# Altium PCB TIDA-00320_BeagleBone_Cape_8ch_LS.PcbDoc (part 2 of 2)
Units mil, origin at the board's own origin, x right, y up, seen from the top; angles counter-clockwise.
Board outline 6250 x 2150 mil, 2 copper layers (Top Layer, Bottom Layer), stack 62 mil thick; 116 components, 142 nets, 397 pads, 432 vias.
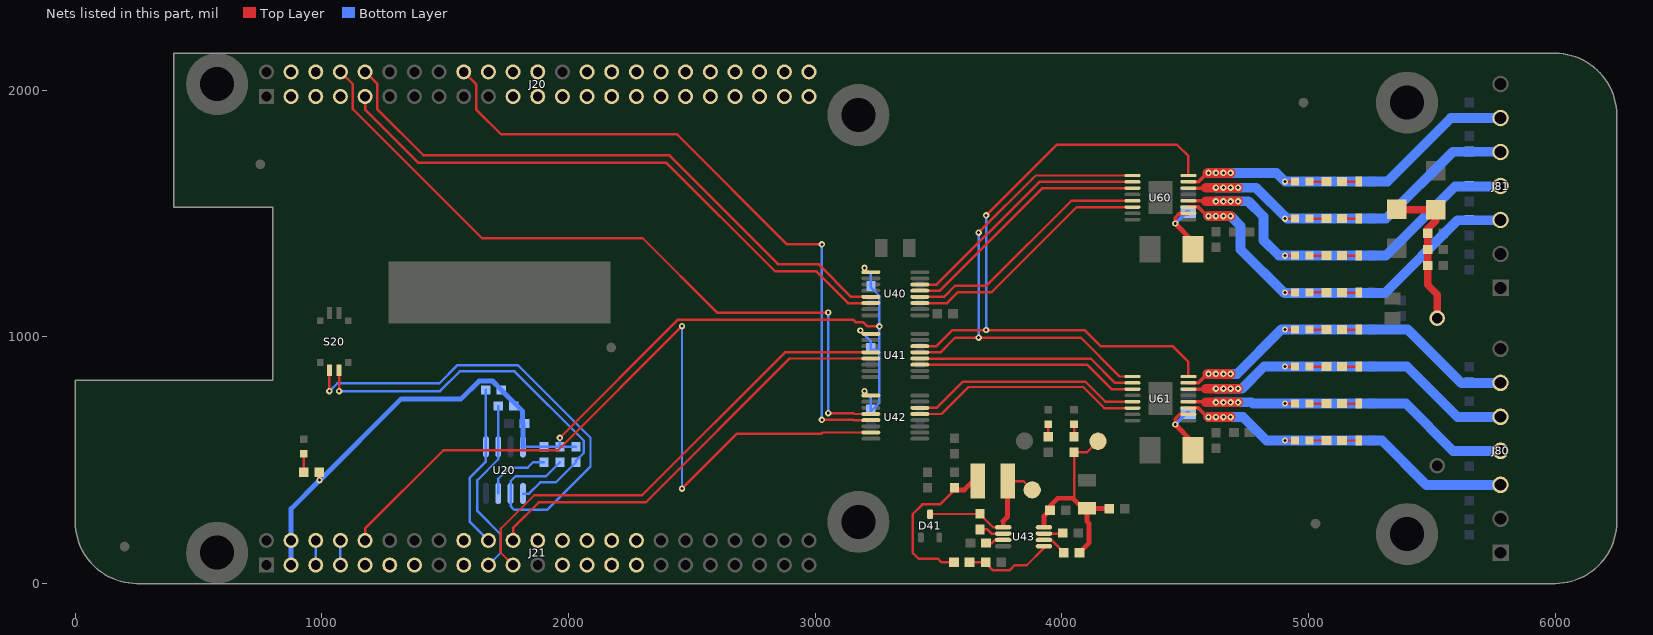
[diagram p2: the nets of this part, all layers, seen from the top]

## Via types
v1: diameter 26, hole 12, Top Layer to Bottom Layer, tented both sides, 318 vias
v2: diameter 20, hole 8, Top Layer to Bottom Layer, tented both sides, 46 vias
v3: diameter 39.37, hole 19.68, Top Layer to Bottom Layer, 36 vias
v4: diameter 50, hole 28, Top Layer to Bottom Layer, tented both sides, 11 vias
v5: diameter 15.75, hole 7.87, Top Layer to Bottom Layer, 10 vias
v6: diameter 26, hole 12, Top Layer to Bottom Layer, 8 vias
v7: diameter 22, hole 12, Top Layer to Bottom Layer, tented both sides, 2 vias
v8: diameter 50, hole 28, Top Layer to Bottom Layer, 1 vias

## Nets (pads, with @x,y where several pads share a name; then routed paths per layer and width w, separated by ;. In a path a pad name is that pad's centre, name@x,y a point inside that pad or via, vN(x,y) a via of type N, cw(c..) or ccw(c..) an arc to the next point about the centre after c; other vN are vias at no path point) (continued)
GPIO2_1: J20.18 U42.5 | length 2711.9
  Top Layer w10: J20.18@1575,2075 1625,2025 1625,1923 1726,1822 2439,1822 2886,1375 v1(3027,1375) ; v1(3027,664) 3154,664 3155.5,662.5 U42.5@3225.59,662.5
  Bottom Layer w10: v1(3027,664) v1(3027,1375)
GPIO3_19: J21.27
GPIO3_21: J21.25
I2C1_SCL: J21.17
I2C1_SDA: J21.18
I2C2_SCL: J21.19 R23.1 U20.6 | length 739.8
  Bottom Layer w10: J21.19@1675,75 1725,125 1725,199 1630,294 1630,419 1715,504 U20.6@1715,554.49 ; U20.6@1714.5,554.98 R23.1@1714.5,720
I2C2_SDA: J21.20 R24.1 U20.5 | length 668
  Bottom Layer w10: R24.1@1665,785 U20.5@1665,554.49 1665,495 1600,430 1600,250 J21.20@1675,175
IN_Y0: U42.13 U61.14 | length 943.1
  Top Layer w10: U42.13@3424.41,687.5 3512.5,687.5 3622,797 4087,797 4172.39,711.61 U61.14@4286.81,711.61
IN_Y1: U42.14 U61.13 | length 940.4
  Top Layer w10: U42.14@3424.41,712.5 3492.5,712.5 3599,819 4095,819 4176.8,737.2 U61.13@4286.81,737.2
IN_Y2: U41.11 U61.11 | length 903.5
  Top Layer w10: U41.11@3424.41,887.5 4102.5,887.5 4201.61,788.39 U61.11@4286.81,788.39
IN_Y3: U41.12 U61.10 | length 902.7
  Top Layer w10: U41.12@3425.28,911.63 4116.63,911.63 4117.5,912.5 4216.02,813.98 U61.10@4286.81,813.98
IN_Y4: U40.11 U60.14 | length 1023.6
  Top Layer w10: U40.11@3424.41,1137.5 3534.92,1137.5 3579.42,1182 3716,1182 4060.61,1526.61 U60.14@4286.81,1526.61
IN_Y5: U40.12 U60.13 | length 1023.8
  Top Layer w10: U40.12@3424.41,1162.5 3522.5,1162.5 3568,1208 3695,1208 4039.2,1552.2 U60.13@4286.81,1552.2
IN_Y6: U40.13 U60.11 | length 1034.7
  Top Layer w10: U40.13@3424.41,1187.5 3505.73,1187.5 3921.61,1603.39 U60.11@4286.81,1603.39
IN_Y7: U40.14 U60.10 | length 1034.9
  Top Layer w10: U40.14@3424.41,1212.5 3492.5,1212.5 3908.98,1628.98 U60.10@4286.81,1628.98
LCD_DATA0: J20.45
LCD_DATA1: J20.46
LCD_DATA2: J20.43
LCD_DATA3: J20.44
LCD_DATA4: J20.41
LCD_DATA5: J20.42
LCD_DATA6: J20.39
LCD_DATA7: J20.40
LCD_DATA8: J20.37
LCD_DATA9: J20.38
LCD_DATA10: J20.36
LCD_DATA11: J20.34
LCD_DATA12: J20.35
LCD_DATA13: J20.33
LCD_DATA14: J20.31
LCD_DATA15: J20.32
LCD_DE: J20.30
LCD_HSYNC: J20.29
LCD_PCLK: J20.28
LCD_VSYNC: J20.27
MMC1_CLK: J20.21
MMC1_CMD: J20.20
MMC1_DAT0: J20.25
MMC1_DAT1: J20.24
MMC1_DAT2: J20.5
MMC1_DAT3: J20.6
MMC1_DAT4: J20.23
MMC1_DAT5: J20.22
MMC1_DAT6: J20.3
MMC1_DAT7: J20.4
NENBL: U41.14 U60.8 U61.8 | length 2730.3
  Top Layer w10: U41.14@3424.41,962.5 3491.5,962.5 3557,1028 4092,1028 4157.5,962.5 4449.5,962.5 4513.19,898.81 U61.8@4513.19,839.57 ; v1(3693,1493) 3979,1779 4468,1779 4513.19,1733.81 U60.8@4513.19,1654.57
  Bottom Layer w10: v1(3693,1028) v1(3693,1493)
NetC47_1: C47.1 C48.1 L40.2 R40.2 R42.2 TP40.1 U43.8 | length 869.3
  Top Layer w10: 4044,346 4050,352 R40.2@4050,532.5 4102.5,532.5 TP40.1@4147,577
  Top Layer w20: U43.8@3927.68,229.5 3927.68,273.68 ; 3929.18,273.68 C48.1@3952.5,297 3952.5,315.5 3983,346 4044,346 4085.09,304.91 C47.1@4103,304.91 ; R42.2@4071.5,125 4110,163.5 4110,244 4103,251 C47.1@4103,304.91 ; L40.2@4192.5,303 4190.59,304.91 C47.1@4103,304.91
NetC49_2: C49.2 U43.7 | length 76.9
  Top Layer w10: U43.7@3927.68,202.48 4000.98,202.48 C49.2@4003.5,205
NetC50_1: C50.1 U43.2 | length 101.4
  Top Layer w10: C50.1@3668,219.5 3698.5,219.5 3715.52,202.48 U43.2@3762.32,202.48
NetC50_2: C50.2 D41.3 L41.1 TP41.1 U43.1 | length 628.4
  Top Layer w10: D41.3@3465,282 3667.5,282 3721.43,228.07 U43.1@3762.32,228.07 ; L41.1@3780.04,415 3845,415 TP41.1@3880,380
  Top Layer w17: U43.1@3762.32,228.07 3762.32,253.32
  Top Layer w20: 3762.32,253.32 3780.04,271.04 L41.1@3780.04,415
NetC62_1: C62.1 D60.1 U60.2 | length 290.2
  Top Layer w15: v1(4460,1460) 4460,1482.86 4477.34,1500.2 U60.2@4512.36,1500.2
  Top Layer w20: v1(4460,1460) 4531.52,1388.48 D60.1@4531.52,1355
  Bottom Layer w15: v1(4460,1460) 4507.09,1507.09 C62.1@4513.65,1507.09
NetC63_1: C63.1 D61.1 U61.2 | length 291.3
  Top Layer w15: v1(4460,645) 4460,667.86 4478.17,686.02 U61.2@4513.19,686.02
  Top Layer w20: v1(4460,645) 4531.52,573.48 D61.1@4531.52,540
  Bottom Layer w15: v1(4460,645) 4507.09,692.09 C63.1@4513.65,692.09
NetC88_1: C88.1 C89.1 C90.1 D96.2 D97.2 RF80.1 | length 628.1
  Top Layer w30: D97.2@5358,1517.74 5359.48,1516.26 D96.2@5516,1516.26 5516,1471.08 5483.5,1438.58 C90.1@5483.5,1420 C89.1@5483.5,1355 5483.5,1210.5 5522,1172 RF80.1@5522,1076.21
NetD20_1: D20.1 R25.1 | length 75
  Top Layer w10: R25.1@926.5,451 D20.1@926.5,525.97
NetD40_1: D40.1 R40.1 | length 50.5
  Top Layer w10: R40.1@4050,595 D40.1@4050,645.47
NetD42_1: D42.1 R46.2 | length 50.5
  Top Layer w10: R46.2@3945,595 D42.1@3945,645.47
NetD80_1: D80.1 R80.2 | length 67.9
  Top Layer w10: R80.2@5136.5,580 D80.1@5204.41,580
NetD81_1: D81.1 R81.2 | length 67.9
  Top Layer w10: R81.2@5136.5,730 D81.1@5204.41,730
NetD82_1: D82.1 R82.2 | length 67.9
  Top Layer w10: R82.2@5136.5,880 D82.1@5204.41,880
NetD83_1: D83.1 R83.2 | length 67.9
  Top Layer w10: R83.2@5136.5,1030 D83.1@5204.41,1030
NetD84_1: D84.1 R84.2 | length 67.9
  Top Layer w10: R84.2@5136.5,1180 D84.1@5204.41,1180
NetD85_1: D85.1 R85.2 | length 67.9
  Top Layer w10: R85.2@5136.5,1330 D85.1@5204.41,1330
NetD86_1: D86.1 R86.2 | length 67.9
  Top Layer w10: R86.2@5136.5,1480 D86.1@5204.41,1480
NetD87_1: D87.1 R87.2 | length 67.9
  Top Layer w10: R87.2@5136.5,1630 D87.1@5204.41,1630
NetD88_1: D88.1 R80.1 | length 69
  Top Layer w10: D88.1@5004.47,580 R80.1@5073.5,580
NetD89_1: D89.1 R81.1 | length 69
  Top Layer w10: D89.1@5004.47,730 R81.1@5073.5,730
NetD90_1: D90.1 R82.1 | length 69
  Top Layer w10: D90.1@5004.49,880.03 R82.1@5073.5,880
NetD91_1: D91.1 R83.1 | length 69
  Top Layer w10: D91.1@5004.47,1029.97 R83.1@5073.5,1030
NetD92_1: D92.1 R84.1 | length 68.7
  Top Layer w10: D92.1@5004.47,1180.29 R84.1@5073.21,1180.29
NetD93_1: D93.1 R85.1 | length 69
  Top Layer w10: D93.1@5004.46,1330.07 R85.1@5073.44,1330.07
NetD94_1: D94.1 R86.1 | length 69
  Top Layer w10: D94.1@5004.47,1479.99 R86.1@5073.5,1480
NetD95_1: D95.1 R87.1 | length 69
  Top Layer w10: D95.1@5004.53,1630 R87.1@5073.5,1630
NetL41_2: L41.2 R44.1 R45.1 | length 658.1
  Top Layer w10: R44.1@3560.5,86 3513,86 3499,100 3420,100 3395,125 3395,281 3435,321 3506,321 R45.1@3565,380
  Top Layer w20: R45.1@3565,380 3605,380 3640,415 L41.2@3659.96,415
NetR20_1: R20.1 U20.3 | length 272.2
  Bottom Layer w10: U20.3@1715,365.51 1715,425 1760,470 1834.65,470 1856.5,491.85 R20.1@1900,491.85
NetR21_1: R21.1 S20.3 U20.2 | length 2162
  Top Layer w10: v1(1030,780) 1030.32,780.32 S20.3@1030.32,864.86
  Bottom Layer w10: v1(1030,780) 1061.87,811.87 1475.87,811.87 1550,886 1794,886 2089,591 2089,475 1913,299 1780,299 1765,314 U20.2@1765,365.51 1765,415 1785,435 1908.15,435 R21.1@1965,491.85
NetR22_1: R22.1 S20.4 U20.1 | length 1593.9
  Top Layer w10: S20.4@1069.68,864.86 1069.68,780.32 v1(1070,780)
  Bottom Layer w10: v1(1070,780) 1479,780 1559,860 1781.43,860 2061.57,579.86 2061.57,529.82 2030,498.25 R22.1@2030,491.85 1948.15,410 1885,410 1840,365 U20.1@1815.51,365
NetR41_2: R41.2 U43.3 | length 75.2
  Top Layer w10: R41.2@3692.5,164 3717,164 3729.89,176.89 U43.3@3762.32,176.89
NetR42_1: R42.1 U43.6 | length 102.9
  Top Layer w10: U43.6@3927.68,176.89 3957.6,176.89 4008.5,125.99 R42.1@4008.5,125
NetR43_2: R43.2 R44.2 U43.5 | length 346.8
  Top Layer w10: R44.2@3638.62,86 3688.5,86 3719.6,54.43 3789.43,54.43 3809,74 3857.94,74 3927.68,143.74 U43.5@3927.68,151.3
PWR_BUT: J21.9
RESET: U41.13 U60.9 U61.9 | length 2094
  Top Layer w10: U41.13@3428.41,937.5 3508.5,937.5 3568,997 4077,997 4234.43,839.57 U61.9@4286.81,839.57 ; v1(3663,1423) 3894.57,1654.57 U60.9@4286.81,1654.57
  Bottom Layer w10: v1(3663,997) v1(3663,1423)
SPI1_CS0: J21.28
SPI1_D0: J21.29
SPI1_D1: J21.30
SPI1_SCLK: J21.31
SYS_5V: J21.7 J21.8 | length 100
  Bottom Layer w10: J21.7@1075,75 J21.8@1075,175
SYS_RESETN: J21.10 U42.7 | length 3191.9
  Top Layer w10: J21.10@1175,175 1175,223 1492,540 1956,540 v1(2460,1044) ; v1(2460,385) 2683.25,608.25 3025.25,608.25 3029.5,612.5 U42.7@3225.59,612.5
  Bottom Layer w10: v1(2460,385) v1(2460,1044)
TIMER4: J20.7
TIMER5: J20.9 U40.6 | length 2428
  Top Layer w10: J20.9@1175,1975 1175,1923 1392,1706 2397,1706 2836,1267 3003,1267 3132.5,1137.5 U40.6@3225.59,1137.5
TIMER6: J20.10 U40.5 | length 2484.5
  Top Layer w10: J20.10@1175,2065.71 1184.3,2065.71 1225,2025.01 1225,1923 1411,1737 2407,1737 2849,1295 3013,1295 3145.5,1162.5 U40.5@3225.59,1162.5
TIMER7: J20.8 U42.4 | length 3023.5
  Top Layer w10: J20.8@1075,2075 1125,2025 1125,1924 1649,1400 2301,1400 2602,1099 v1(3053,1099) ; v1(3053,691) 3154,691 3157.5,687.5 U42.4@3225.59,687.5
  Bottom Layer w10: v1(3053,691) v1(3053,1099)
UART1_RXD: J21.26
UART1_TXD: J21.24
UART2_RXD: J21.22 U41.5 | length 1785.4
  Top Layer w10: J21.22@1775,175 1775,225 1879,329 2313,329 2896.5,912.5 U41.5@3225.59,912.5
UART2_TXD: J21.21 U41.4 | length 1964.7
  Top Layer w10: J21.21@1775,75 1725,125 1725,222 1861,358 2298,358 2877.5,937.5 U41.4@3225.59,937.5
UART4_RXD: J21.11
UART4_TXD: J21.13
VDD_3V3B: C20.1 C40.1 C41.1 C42.1 J21.3 J21.4 R20.2 R21.2 R22.2 R23.2 R24.2 R25.2 U20.8 U40.1 U41.1 U42.1 | length 4285.8
  Top Layer w10: v1(1965,591) 2444,1070 3154,1070 3165,1059 3196,1059 3212,1043 v1(3260,1043) ; v1(3183,1026) 3196.5,1012.5 U41.1@3225.59,1012.5 ; v1(3200,1280) 3217.5,1262.5 U40.1@3225.59,1262.5
  Top Layer w20: v1(990,419) R25.2@990,450.5
  Bottom Layer w10: U20.8@1815.35,554.84 R20.2@1900,554.84 R21.2@1965,554.84 ; v1(1965,591) R21.2@1965,554.84 ; R22.2@2030,554.84 R21.2@1965,554.84 ; v1(3183,1026) 3225,984 3225,948.62 3256.62,948.62 ; v1(3200,780) 3225,755 C42.1@3225,698.62 ; v1(3200,1280) 3226,1254 C40.1@3226,1206.5 3226,1201 3260,1167 3260,731.63 C42.1@3225,696.63
  Bottom Layer w20: J21.3@875,75 J21.4@875,175 875,304 v1(990,419) ; v1@991,418 1322,749 1564.84,749 1637.42,821.57 1691.59,821.57 1727.5,785.67 R24.2@1727.5,785 1813.62,698.87 C20.1@1813.62,649 ; U20.8@1815,554.49 C20.1@1815,649
VDD_5V: J21.5 J21.6 | length 100
  Bottom Layer w10: J21.5@975,75 J21.6@975,175
VDD_ADC: J21.32
Y0: C80.1 D88.2 J80.3 U61.3 | length 1521.1
  Top Layer w10: v1(4905,580) D88.2@4945.41,580
  Top Layer w15: U61.3@4513.19,711.61 4553.39,711.61 v1@4590,675
  Top Layer w40: v1(4595,675) v1(4685,675)
  Bottom Layer w40: v1(4595,675) 4735,675 4830,580 v1(4905,580) 5298,580 5478,400 5777,400 J80.3@5779,402
  other v1: 4625,675
  other v6: 4655,675
Y1: C81.1 D89.2 J80.4 U61.4 | length 1467.8
  Top Layer w10: v1(4905,730) D89.2@4945.41,730
  Top Layer w15: U61.4@4513.19,737.2 4575,737.2
  Top Layer w40: 4585,735 v1(4715,735)
  Bottom Layer w40: v1(4625,735) 4770,735 4775,730 v1(4905,730) 5395,730 5587,538 J80.4@5779,538
  other v1: 4685,735
  other v6: 4655,735
Y2: C82.1 D90.2 J80.5 U61.6 | length 1508.1
  Top Layer w10: v1(4905,880.03) D90.2@4945.44,880.03
  Top Layer w15: U61.6@4513.19,788.39 4575,788.39
  Top Layer w40: 4585,790 v1(4715,790)
  Bottom Layer w40: v1(4625,790) 4730,790 4820.03,880.03 v1(4905,880.03) 5399.97,880.03 5604,676 J80.5@5779,676
  other v1: 4685,790
  other v6: 4655,790
Y3: C83.1 D91.2 J80.6 U61.7 | length 1575.5
  Top Layer w10: v1(4905,1029.97) D91.2@4945.41,1029.97
  Top Layer w15: U61.7@4513.19,813.98 4553.98,813.98 v1@4590,850
  Top Layer w40: v1@4590,850 v1(4685,850)
  Bottom Layer w40: v1(4595,850) 4710,850 4889.97,1029.97 v1(4905,1029.97) 5403.03,1029.97 5619.99,813.01 J80.6@5779,813.02
  other v1: 4625,850
  other v6: 4655,850
Y4: C84.1 D92.2 J81.3 U60.3 | length 1719.1
  Top Layer w10: v1@4905.29,1180.29 D92.2@4945.41,1180.29
  Top Layer w15: U60.3@4513.19,1526.61 4553.39,1526.61 4590,1490 v1(4595,1490)
  Top Layer w40: v1(4595,1490) v6(4655,1490) v1(4685,1490)
  Bottom Layer w40: v1(4595,1490) v1(4685,1490) 4725,1450 4725,1355 4901.92,1178.08 5310.08,1178.08 5605,1473 J81.3@5780,1473
  other v1: 4905,1180 4625,1490
Y5: C85.1 D93.2 J81.4 U60.4 | length 1649.6
  Top Layer w10: v1(4905,1330) D93.2@4945.47,1330
  Top Layer w15: U60.4@4513.19,1552.2 4575,1552.2
  Top Layer w40: 4585,1550 v1(4715,1550)
  Bottom Layer w40: v1(4625,1550) 4756,1550 4818,1488 4818,1392 4880,1330 v1(4905,1330) 5315,1330 5595,1610 J81.4@5779,1610
  other v1: 4685,1550
  other v6: 4655,1550
Y6: C86.1 D94.2 J81.5 U60.6 | length 1550.2
  Top Layer w10: v1(4905,1480) D94.2@4945.41,1479.99
  Top Layer w15: U60.6@4513.19,1603.39 4575,1603.39
  Top Layer w40: 4585,1605 v1(4715,1605)
  Bottom Layer w40: v1(4625,1605) 4788,1605 4913,1480 5315,1480 5586,1751 J81.5@5779,1751
  other v1: 4685,1605
  other v6: 4655,1605
Y7: C87.1 D95.2 J81.6 U60.7 | length 1532.3
  Top Layer w10: v1(4905,1630) D95.2@4945.47,1630
  Top Layer w15: U60.7@4513.19,1628.98 4553.98,1628.98 v1@4590,1665
  Top Layer w40: v1@4590,1665 v1(4685,1665)
  Bottom Layer w40: v1(4595,1665) 4870,1665 v1(4905,1630) 5320,1630 5577.45,1887.45 J81.6@5779,1887.45
  other v1: 4625,1665
  other v6: 4655,1665
pads on no net: FID1.1 FID2.1 FID3.1 FID4.1 FID5.1 LBL1.0 Logo1.0 MH1.1 MH2.1 MH3.1 MH4.1 MH5.1 MH6.1 S20.M1 S20.M2 S20.M3 S20.M4 U40.7 U41.7 U60.15 U61.15
copper on no net:
  other v3: 575,27.56 490.61,76.28 659.39,76.28 5400,102.56 5315.61,151.28 5484.39,151.28 3175,152.56 490.61,173.72 659.39,173.72 3090.61,201.28 3259.39,201.28 575,222.44 5315.61,248.72 5484.39,248.72 5400,297.44 3090.61,298.72 3259.39,298.72 3175,347.44 3175,1802.56 3090.61,1851.28 3259.39,1851.28 5400,1852.56 5315.61,1901.28 5484.39,1901.28 575,1927.56 3090.61,1948.72 3259.39,1948.72 490.61,1976.28 659.39,1976.28 3175,1997.44 5315.61,1998.72 5484.39,1998.72 5400,2047.44 490.61,2073.72 659.39,2073.72 575,2122.44

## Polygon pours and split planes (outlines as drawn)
GND_EARTH on Top Layer "GND-Earth-Net" (solid, pour order 10): 5529,2130 6230,2130 6230,20 5529,20
GND_ISO on Top Layer "Top Layer-GND_iso" (solid, remove dead copper, pour order 9): 3359,2130 3359,20 5601,20 5601,2130
DGND on Top Layer "Top Layer-DGND" (solid, remove dead copper, pour order 7): 20,2130 20,20 3300,20 3300,2130
GND_ISO on Bottom Layer "Bottom Layer-GND_iso" (solid, pour order 8): 3359,2130 3359,20 5601,20 5601,2130
DGND on Bottom Layer "Bottom Layer-DGND" (solid, remove dead copper, pour order 6): 20,2130 20,20 3300,20 3300,2130

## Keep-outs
Keep-Out Layer:
  lines w10: -5,825 cw(c0,825) 0,830 ; -5,825 cw(c0,825) 0,830 ; -5,825 -5,250 ccw(c250,250) 250,-5 6000,-5 ccw(c6000,250) 6255,250 6255,1900 ccw(c6000,1900) 6000,2155 400,2155 ; 0,830 795,830 795,1520 400,1520 ; 395,1525 ccw(c400,1525) 400,1520 ; 395,1525 ccw(c400,1525) 400,1520 ; 395,1525 395,2150 ; 395,2150 cw(c400,2150) 400,2155 ; 395,2150 cw(c400,2150) 400,2155
  text ".Layer_Name" at 577,-858.49 h60

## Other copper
Top Layer:
  pour cut-out: 3430,2010 3809.93,2009.98 3810,1775 3430,1775
  text ".CopyrightYear" at 3565,1915 h60
  text "©" at 3460,1910 h105
  text "TI" at 3465,1810 h60
  text ".Layer_Name" at 577,-858.49 h60
Bottom Layer:
  text "UL94V-0" at 5015,200 h60
  text "MADE IN GERMANY" at 5015,110 h60
  text ".Layer_Name" at 577,-858.49 h60

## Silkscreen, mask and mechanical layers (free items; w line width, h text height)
Top Overlay:
  region: 4581,2118 4281,2118 4281,2018 4581,2018
  lines w10: 3320,110 3320,2050 ; 3340,110 3340,2050
  text ".PRJ_Number" at 3489,2038 h60
  text ".PCB_Rev" at 4101,2038 h60
  text "-" at 4206,2038 h60
  text "+24" at 6106,1975 h40
  text "Y7" at 6111,1863 h40
  text "P8-Header" at 1613,1810 h60
  text "Y6" at 6111,1728 h40
  text "Y5" at 6111,1588 h40
  text "500V Isolation" at 3406,1565 h40 r90
  text "Y4" at 6111,1453 h40
  text "GND" at 6113,1315 h40
  text "E" at 6132,1201 h40
  text "+24" at 6104,948 h40
  text "Y3" at 6111,792 h40
  text "Y2" at 6111,657 h40
  text "5V" at 3814,622 h40
  text "24V" at 4091,622 h40
  text "Y1" at 6111,517 h40
  text "Y0" at 6111,377 h40
  text "P9-Header" at 1613,269 h60
  text "GND" at 6108,242 h40
  text "E" at 6131,105 h40
  text ".Layer_Name" at 577,-858.49 h60
Bottom Overlay:
  text ".Layer_Name" at 577,-858.49 h60
Top Paste:
  text ".Layer_Name" at 577,-858.49 h60
Bottom Paste:
  text ".Layer_Name" at 577,-858.49 h60
Top Solder:
  text ".Layer_Name" at 577,-858.49 h60
  text ".Layer_Name" at 577,-858.49 h60
Bottom Solder:
  text ".Layer_Name" at 577,-858.49 h60
Drill Guide:
  text ".Layer_Name" at 577,-858.49 h60
M1 Board Outline:
  the board outline again, w10
  text ".Layer_Name" at 577,-858.49 h60
M2 Board Dimensions:
  rectangle: 0,-285.5 125,-160.5
  rectangle: 125,-410.5 500,-285.5
  lines w7: 0,-285.5 1000,-285.5 ; 125,-410.5 125,-160.5 ; 250,-410.5 250,-160.5 ; 500,-410.5 500,-160.5 ; 750,-410.5 750,-160.5 ; 0,-410.5 1000,-410.5 1000,-160.5 0,-160.5 0,-410.5
  text ".Layer_Name" at 577,-858.49 h60
M3 3D STEP Top:
  pour cut-out: 5500,1475 5500,1230 5675,1230 5675,1475
  pour cut-out: 4197,662.28 4576.93,662.26 4577,427.28 4197,427.28
  text ".Layer_Name" at 577,-858.49 h60
M4 3D STEP Bottom:
  text ".Layer_Name" at 577,-858.49 h60
M5 Assembly Top:
  lines w10: -292,-930.17 6308,-930.17 ; -292,-726.83 6310,-726.83 ; -292,-523.5 -292,-1133.5 3713,-1133.5 6310,-1133.5 6310,-523.5 -291.5,-523.5 -291.5,-1133.5 1284,-1133.5 ; 2173,-1133.5 2173,-523.5 ; 3440,-726.83 3440,-523.5 ; 4280,-726.83 4280,-523.5 ; 4902,-1140 4902,-937.17
  text "COMPONENTS MARKED 'DNP' SHOULD NOT BE POPULATED." at 1153.5,-318.5 h60
  text "ASSEMBLY VARIANT:" at 1153,-434 h60
  text ".VariantName" at 2189,-434 h60
  text "PCB VIEWED FROM TOP SIDE" at -228.5,-655.67 h60
  text "BOARD #:" at 2248,-655.67 h60
  text ".PRJ_Number" at 2793.5,-655.67 h60
  text "REV:" at 3638,-655.67 h60
  text ".PCB_Rev" at 3929.5,-655.67 h60
  text "SVN REV:" at 4476,-655.67 h60
  text ".VersionControl_RevNumber" at 4982,-655.67 h60
  text "IGNORE ->" at -228.5,-858.49 h60
  text "PLOT NAME =" at -228.5,-1064.34 h60
  text ".plot_File_Name" at 577,-1064.34 h60
  text "GENERATED    :" at 2250,-1064.34 h60
  text ".Print_Date" at 3119.5,-1064.34 h60
  text ".Print_Time" at 3848.5,-1064.34 h60
  text "TEXAS INSTRUMENTS" at 5113,-1064.34 h60
M6 Assembly Bottom:
  lines w10: -292.5,-727.33 6309.5,-727.33 ; -290.5,-930.67 6309.5,-930.67 ; 1115.5,-1140.5 1115.5,-937.67 ; 1737.5,-727.33 1737.5,-524 ; 2577.5,-727.33 2577.5,-524 ; 3844.5,-1134 3844.5,-524 ; 4733.5,-1134 6309,-1134 6309,-524 -292.5,-524 -292.5,-1134 2304.5,-1134 6309.5,-1134 6309.5,-524
  text "COMPONENTS MARKED 'DNP' SHOULD NOT BE POPULATED." at 6102,-318 h60
  text ".VariantName" at 5058,-434 h60
  text "ASSEMBLY VARIANT:" at 6097,-434 h60
  text ".VersionControl_RevNumber" at 1035.5,-656.17 h60
  text "SVN REV:" at 1541.5,-656.17 h60
  text ".PCB_Rev" at 2088,-656.17 h60
  text "REV:" at 2379.5,-656.17 h60
  text ".PRJ_Number" at 3224,-656.17 h60
  text "BOARD #:" at 3769.5,-656.17 h60
  text "PCB VIEWED FROM BOTTOM SIDE" at 6246,-656.17 h60
  text "IGNORE ->" at 2547.85,-858.49 h60
  text "TEXAS INSTRUMENTS" at 904.5,-1064.84 h60
  text ".Print_Time" at 2169,-1064.84 h60
  text ".Print_Date" at 2898,-1064.84 h60
  text "GENERATED    :" at 3767.5,-1064.84 h60
  text ".plot_File_Name" at 5440.5,-1064.84 h60
  text "PLOT NAME =" at 6246,-1064.84 h60
M9 Title Sheet:
  drawing of 57 lines, arcs and shapes, not listed
  text "1" at 739.84,8036.5 h70
  text "2" at 3235.5,8036.5 h70
  text "3" at 5724.84,8036.5 h70
  text "4" at 8231.51,8036.5 h70
  text "5" at 10730.5,8036.5 h70
  text "6" at 13235.5,8036.5 h70
  text "A" at -416.5,6893.5 h70
  text "A" at 14383.5,6893.5 h70
  text "B" at -416.5,4513.5 h70
  text "B" at 14383.5,4513.5 h70
  text "C" at -416.5,2138.5 h70
  text "C" at 14383.5,2138.5 h70
  text "PROJECT TITLE:" at 11343.5,277.5 h45
  text ".PRJ_Title" at 11393.5,144.17 h70
  text "DESIGNED FOR:" at 11343.5,-23.5 h45
  text ".PRJ_Customer" at 11393.5,-163.5 h70
  text "D" at -416.5,-231.5 h70
  text "D" at 14383.5,-231.5 h70
  text "FILE NAME:" at 11343.5,-323.5 h45
  text ".PCB_File_Name_No_Path" at 11393.5,-443.5 h70
  text "Texas Instruments (TI) and/or its licensors do not warrant the accuracy or completeness of this specification" at 6374,-605.34 h45
  text "ENGINEER:" at 11343.5,-613.5 h45
  text "LAYOUT BY:" at 12848.5,-613.5 h45
  text "or any information contained therein. TI and/or its licensors do not warrant that this design will meet" at 6329.01,-718 h45
  text ".PRJ_Engineer" at 11393.5,-768.49 h70
  text ".PCB_Layout" at 12899,-768.49 h70
  text "the specifications, will be suitable for your application or fit for any particular purpose, or will operate in" at 6329.01,-830.67 h45
  text ".Layer_Name" at 577,-858.49 h60
  text "ALTIUM DESIGNER VERSION:" at 12848.5,-923.5 h45
  text "an implementation. TI and/or its licensors do not warrant that the design is production worthy. You should" at 6329.01,-943.33 h45
  text "completely validate and test your design implementation to confirm the system functionality for your application." at 6374,-1056 h45
  text ".print_Scale" at 11393.5,-1056.83 h70
  text ".Application_BuildNumber" at 12899,-1056.83 h70
  text "1" at 739.84,-1263.5 h70
  text "2" at 3235.5,-1263.5 h70
  text "3" at 5724.84,-1263.5 h70
  text "4" at 8231.51,-1263.5 h70
  text "5" at 10730.5,-1263.5 h70
  text "6" at 13235.5,-1263.5 h70
M10 Fab Notes:
  drawing of 185 lines, arcs and shapes, not listed
  text "DESIGN INFORMATION" at 12381.02,5910 h60
  text "MIN. TRACK WIDTH:" at 11736.46,5730 h60
  text "8" at 12832.7,5730 h60
  text "MIL" at 12987.46,5730 h60
  text "MIN. CLEARANCE:" at 11736.46,5598 h60
  text "0.2" at 12772.7,5598 h60
  text "mm" at 12987.46,5598 h60
  text "MIN. VIA PAD SIZE:" at 11736.46,5466 h60
  text "24" at 12802.71,5466 h60
  text "MIL" at 12987.46,5466 h60
  text "0.05mm (2MIL)" at 12431.46,5324.29 h60
  text "MINIMUM ANNULAR RING" at 11407.23,5320 h60
  text "EXTERNAL" at 13139.46,5320 h60
  text "PER" at 11607.23,5202 h60
  text "IPC-D-275 CLASS 2 LEVEL C" at 11827.23,5202 h60
  text "MIL, HOLES" at 13315.46,5089.71 h60
  text "+/-" at 12923,5089 h60
  text "+/-" at 13777,5089 h60
  text "REGISTRATION TOLERANCES:" at 11407.23,5084 h60
  text "METAL" at 12607,5084 h60
  text "5" at 13183.2,5084 h60
  text "3" at 14016.2,5084 h60
  text "MIL" at 14132.46,5084 h60
  text "MATERIAL:" at 11332.46,4874.54 h60
  text "FR-4 High Tg" at 12318.9,4734.21 h60
  text "FR-408" at 11753.46,4725.64 h60
  text "X" at 12165.46,4725.64 h60
  text "OTHER" at 13241.46,4725.64 h60
  text "62 MIL (1.6mm) +/-10%" at 12073.56,4562.92 h60
  text "THICKNESS:" at 11407.23,4558.64 h60
  text "X" at 11945.4,4558.64 h60
  text "OTHER" at 13358.46,4558.64 h60
  text "TOLERANCE:" at 11407.23,4400.64 h60
  text "X" at 12246.53,4400.64 h60
  text "ANSI IPC-6012 TYPE 3 CLASS 2" at 12433.48,4400.64 h60
  text "OTHER +/-" at 12433.46,4244.64 h60
  text "BOW & TWIST:" at 11407.23,4087.64 h60
  text "X" at 12246.53,4087.64 h60
  text "ANSI IPC-6012 TYPE 3 CLASS 2" at 12433.48,4087.64 h60
  text "OTHER +/-" at 12433.46,3929.13 h60
  text "DRILLING:" at 11332.46,3790.64 h60
  text "REFERENCE:" at 11407.23,3673.64 h60
  text "X" at 12055.46,3673.64 h60
  text "AS SHOWN" at 12242.46,3673.64 h60
  text "X" at 12956.46,3673.64 h60
  text "NC_DRILL FILES" at 13093.46,3673.64 h60
  text "PTH MIN COPPER THICKNESS:" at 11407.23,3515.64 h60
  text "X" at 12757.46,3515.64 h60
  text "1MIL" at 12894.46,3515.64 h60
  text "OTHER" at 13391.46,3515.64 h60
  text "BOARD FINISH:" at 11332.46,3356.64 h60
  text "SILKSCREEN:" at 11487.68,3238.64 h60
  text "X" at 12436.46,3238.64 h60
  text "TOP" at 12562.46,3238.64 h60
  text "X" at 12946.46,3238.64 h60
  text "BOTTOM" at 13073.46,3238.64 h60
  text "SILKSCREEN COLOR:" at 11487.68,3071.64 h60
  text "X" at 12435.42,3071.64 h60
  text "WHITE" at 12562.46,3071.64 h60
  text "OTHER" at 13073.46,3071.64 h60
  text "SOLDER RESIST COLOR:" at 11487.68,2901.64 h60
  text "X" at 12055.42,2742.44 h60
  text "GREEN" at 12182.46,2742.44 h60
  text "BLUE" at 12773.46,2742.44 h60
  text "OTHER" at 13311.46,2742.44 h60
  text "IMMERSION GOLD (ENIG)" at 12393.46,2553.92 h60
  text "ENEPIG" at 13731,2550.64 h60
  text "SURFACE FINISH:" at 11332.46,2549.64 h60
  text "X" at 12206.51,2549.64 h60
  text "IMM. TIN/SILVER OR EQUIV" at 11662,2392.64 h60
  text "OTHER" at 13093.46,2392.64 h60
  text "ARRAY/PANEL:" at 11332.46,2213.64 h60
  text "CUT AND TRIM PER MECH LAYER 1" at 12393.46,2209.35 h60
  text "N.C. ROUTE" at 12393.46,2057.64 h60
  text "X" at 13072.46,2057.64 h60
  text "V. SCORE" at 13259.46,2057.64 h60
  text "CERTIFICATION:" at 11332.46,1920.64 h60
  text "MATERIALS AND WORKMANSHIP FOR ALL PCBS" at 12057.46,1920.64 h60
  text "TO MEET OR EXCEED THE REQUIREMENTS OF:" at 12057.46,1822.64 h60
  text "X" at 11683.96,1686.13 h60
  text "ANSI IPC-A-600F CLASS ->" at 11822.96,1686.13 h60
  text "X" at 13462.02,1686.13 h60
  text "2" at 13580.96,1686.14 h60
  text "1" at 13265.96,1684.64 h60
  text "3" at 13934.96,1684.64 h60
  text "X" at 11686.02,1526.64 h60
  text "UL 94V-0" at 11822.96,1526.64 h60
  text "X" at 12498.02,1526.64 h60
  text "RoHS" at 12634.96,1526.64 h60
  text "OTHER" at 13279.36,1526.64 h60
  text "PER ORDER" at 13676.42,1526.64 h60
  text "ADDITIONAL REQUIREMENTS:" at 11332.46,1385.64 h60
  text "MICROSECTION:" at 11407.23,1270.64 h60
  text "YES" at 12312.96,1270.64 h60
  text "REQUIRED" at 13174.46,1114.49 h60
  text "BARE BOARD ELEC. TEST:" at 11407.23,1111.64 h60
  text "NONE" at 12712.96,1111.64 h60
  text "X" at 13047.46,1111.64 h60
  text "PER ORDER" at 13766.46,1111.64 h60
  text "MANUFACTURER'S UL:" at 11407.23,954.64 h60
  text "RAIL" at 12572.96,950.35 h60
  text "METAL" at 13064.77,950.35 h60
  text "X" at 13440,950 h60
  text "SILK" at 13576.46,950.35 h60
  text ".Layer_Name" at 577,-858.49 h60
M11 Gerber Information:
  lines w10: -292,-930.17 6308,-930.17 ; -292,-726.83 6310,-726.83 ; -292,-523.5 -292,-1133.5 3713,-1133.5 6310,-1133.5 6310,-523.5 -291.5,-523.5 -291.5,-1133.5 1284,-1133.5 ; 2173,-1133.5 2173,-523.5 ; 3440,-726.83 3440,-523.5 ; 4280,-726.83 4280,-523.5 ; 4902,-1140 4902,-937.17
  text "ALL ARTWORK VIEWED FROM TOP SIDE" at -228.5,-655.67 h60
  text "BOARD #:" at 2248,-655.67 h60
  text ".PRJ_Number" at 2793.5,-655.67 h60
  text "REV:" at 3638,-655.67 h60
  text ".PCB_Rev" at 3929.5,-655.67 h60
  text "SVN REV:" at 4476,-655.67 h60
  text ".VersionControl_RevNumber" at 4982,-655.67 h60
  text "LAYER NAME =" at -228.5,-858.49 h60
  text "PLOT NAME =" at -228.5,-1064.34 h60
  text ".plot_File_Name" at 577,-1064.34 h60
  text "GENERATED    :" at 2250,-1064.34 h60
  text ".Print_Date" at 3119.5,-1064.34 h60
  text ".Print_Time" at 3848.5,-1064.34 h60
  text "TEXAS INSTRUMENTS" at 5113,-1064.34 h60
M12 Stackup:
  lines w6: 11360,7460 13910,7460 ; 11360,7564.4 13910,7564.4 ; 11300,6975 ccw(c11334,6975) 11334,6941 13936,6941 ccw(c13936,6975) 13970,6975 13970,7681 ccw(c13936,7681) 13936,7715 11334,7715 ccw(c11334,7681) 11300,7681 11300,6975
  text "The Stackup Legend below this is static." at 11605.5,7874.5 h60
  text "If you change the stackup, update the Legend." at 11615.5,7784.5 h60
  text "Layer Stack Up Detail for: Ref_Design.PcbDoc" at 11360,7597.1 h57
  text "Layer" at 11360,7525.4 h24
  text "Gerber" at 12255.81,7525.4 h24
  text "Copper" at 12819.33,7525.4 h24
  text "Dielectric" at 13422.04,7525.4 h24
  text "Name" at 11360,7477.4 h24
  text "Document" at 12255.81,7477.4 h24
  text "Thickness" at 12819.33,7477.4 h24
  text "Material" at 13422.04,7477.4 h24
  text "Top Solder Mask" at 11360,7384.44 h34
  text "(.GTS)" at 12255.81,7384.44 h34
  text "Solder Resist" at 13422.04,7384.44 h34
  text "Top Layer" at 11360,7287.69 h34
  text "(.GTL)" at 12255.81,7287.69 h34
  text "1.4mil" at 12819.33,7287.69 h34
  text "FR-4" at 13422.04,7239.31 h34
  text "Bottom Layer" at 11360,7190.94 h34
  text "(.GBL)" at 12255.81,7190.94 h34
  text "1.4mil" at 12819.33,7190.94 h34
  text "Bottom Solder Mask" at 11360,7094.19 h34
  text "(.GBS)" at 12255.81,7094.19 h34
  text "Solder Resist" at 13422.04,7094.19 h34
  text ".Layer_Name" at 577,-858.49 h60
M13 Component Bodies Top:
  text ".Layer_Name" at 577,-858.49 h60
M14 Component Bodies Bottom:
  text ".Layer_Name" at 577,-858.49 h60
M15 Courtyards Top:
  text ".Layer_Name" at 577,-858.49 h60
M16 Courtyards Bottom:
  text ".Layer_Name" at 577,-858.49 h60
Drill Drawing:
  text ".legend" at 6377.5,1065.5 h60
  text "Drill Table" at 6402.5,880.5 h60
  text ".Layer_Name" at 577,-858.49 h60

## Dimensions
0,0 to 0,2150 on M2 Board Dimensions
0,-410.5 to 1000,-410.5 on M2 Board Dimensions
6250,0 to 0,0 on M2 Board Dimensions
